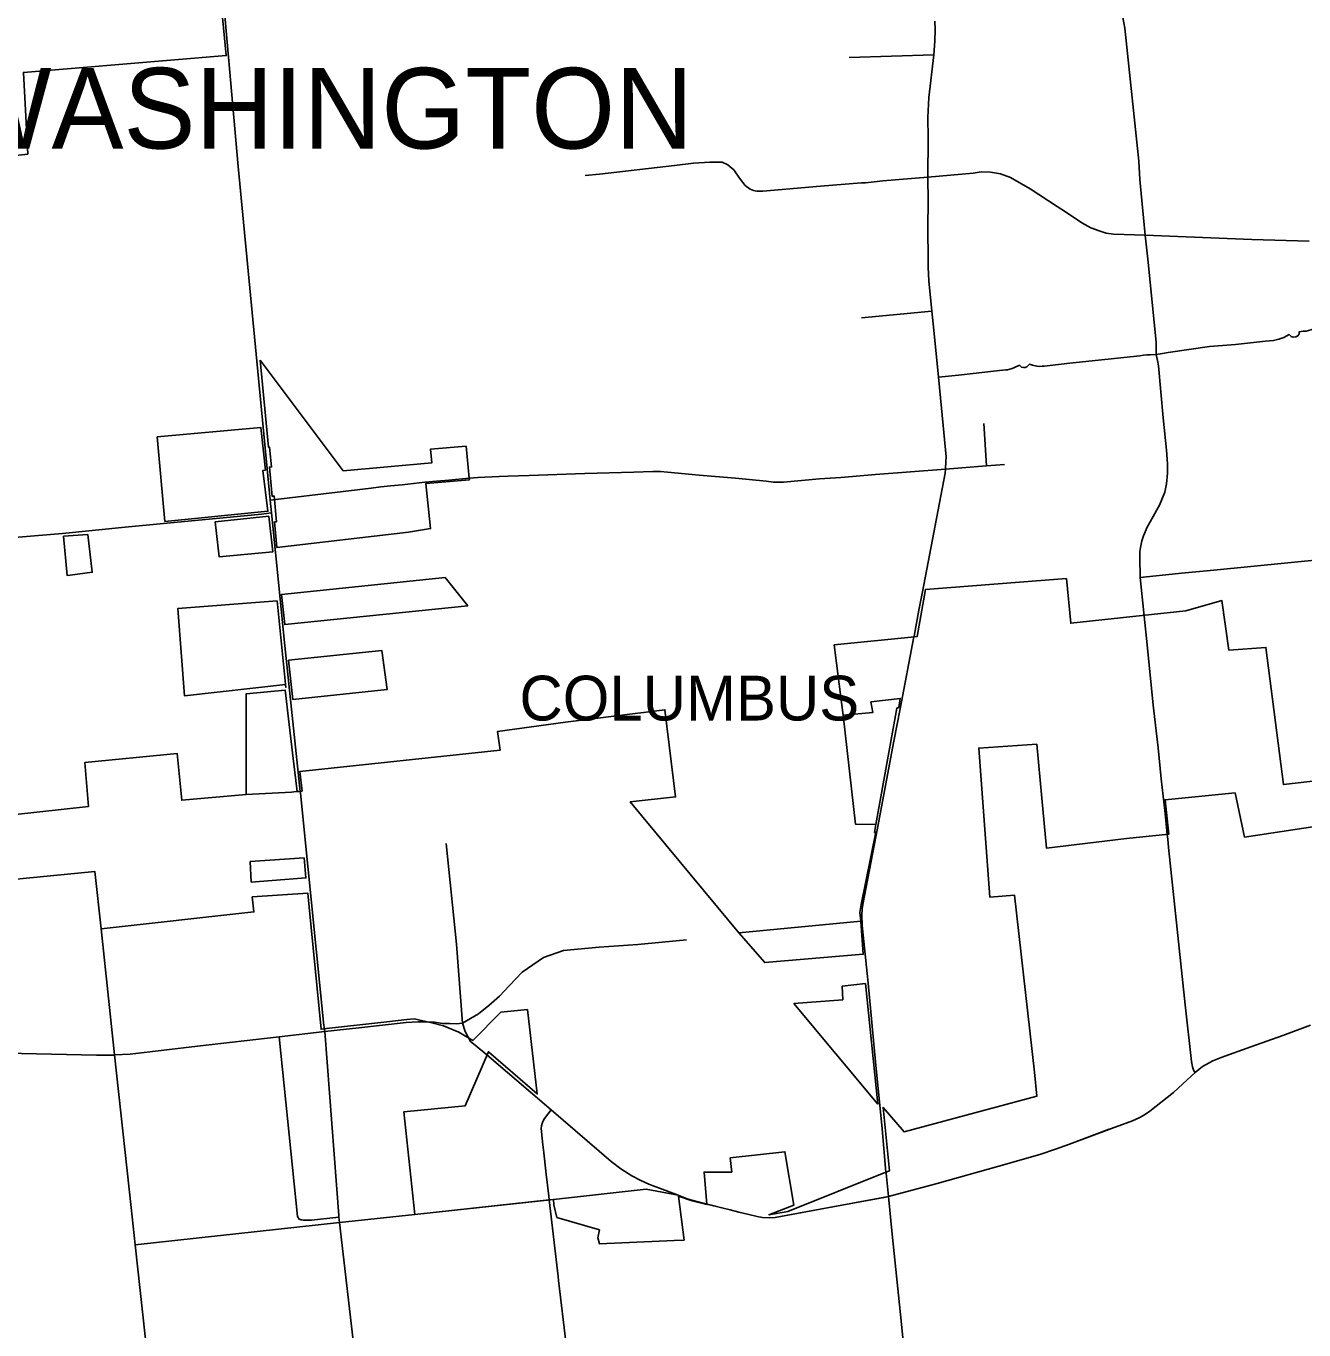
# Model space of a CAD drawing. Extents: x 1729596 to 1934326, y 644115 to 911751.
# Drawn here: x 1774170 to 1788422, y 747751 to 762296 of the extents above; entities that cross this region are included whole.
import ezdxf

# ---------------------------------------------------------------- set-up
doc = ezdxf.new("R2010")
doc.units = 0
for name, color, linetype in [('GM_X_City_Street', 7, 'Continuous'), ('GM_X_Corporation', 7, 'Continuous'), ('GM_X_Corporation_Text', 7, 'Continuous'), ('GM_X_County_Road', 7, 'Continuous'), ('GM_X_Township', 7, 'Continuous'), ('GM_X_Township_Road', 7, 'Continuous'), ('GM_X_Township_Text', 7, 'Continuous')]:
    doc.layers.add(name, color=color, linetype=linetype)

msp = doc.modelspace()

# ---------------------------------------------------------------- linework, layer by layer
at = {"layer": 'GM_X_City_Street'}
for points in [[(1776894, 757007), (1776536, 760730), (1776379, 762498), (1776312, 763238), (1776297, 763289)], [(1784074, 755492), (1784128, 755781), (1784167, 755984), (1784420, 757310), (1784425, 757355), (1784429, 757440), (1784431, 757489), (1784381, 758034), (1784347, 758381), (1784296, 758904), (1784274, 759116), (1784240, 759453), (1784230, 759608), (1784232, 759677), (1784229, 760052), (1784230, 760338), (1784227, 760609), (1784231, 761045), (1784227, 761277), (1784240, 761501), (1784293, 761975), (1784305, 762129), (1784308, 762257), (1784306, 762353)], [(1786597, 756146), (1786591, 756364), (1786591, 756433), (1786599, 756480), (1786616, 756555), (1786633, 756609), (1786673, 756706), (1786740, 756826), (1786781, 756898), (1786810, 756950), (1786870, 757096), (1786891, 757189), (1786900, 757307), (1786900, 757411), (1786891, 757566), (1786854, 757927), (1786800, 758507), (1786789, 758566), (1786774, 758633), (1786775, 758765), (1786733, 759178), (1786683, 759695), (1786650, 759962), (1786616, 760352), (1786592, 760584), (1786580, 760788), (1786424, 762272), (1786390, 762450)], [(1783351, 761947), (1784293, 761975)], [(1781403, 760741), (1781614, 760766), (1781798, 760777), (1781933, 760777), (1781997, 760747), (1782023, 760726)], [(1780404, 760630), (1780564, 760644), (1781403, 760741)], [(1782023, 760726), (1782065, 760691), (1782129, 760598), (1782192, 760517), (1782245, 760477), (1782283, 760463), (1782319, 760456), (1782381, 760453)], [(1783489, 760546), (1783531, 760549), (1783727, 760569), (1784227, 760609)], [(1784227, 760609), (1784735, 760656), (1784822, 760669), (1784927, 760665), (1785037, 760648), (1785151, 760606), (1785370, 760479), (1785672, 760283), (1785762, 760223), (1785944, 760103), (1786045, 760047), (1786138, 760011), (1786218, 759985), (1786298, 759975), (1786650, 759962), (1787842, 759914), (1788482, 759895)], [(1782381, 760453), (1782386, 760453), (1783031, 760512), (1783489, 760546)], [(1783488, 759043), (1784274, 759116)], [(1788366, 758855), (1788370, 758860), (1788370, 758887), (1788413, 758891), (1788448, 758894), (1788498, 758907), (1788586, 758939), (1788903, 759054), (1789110, 759123)], [(1785443, 758502), (1785447, 758501), (1785472, 758500), (1785504, 758503), (1785525, 758504), (1785812, 758536), (1786594, 758619), (1786632, 758624), (1786670, 758627), (1786708, 758629), (1786774, 758633), (1786846, 758644), (1786908, 758654), (1787368, 758722), (1787661, 758743), (1787994, 758780), (1788083, 758790), (1788142, 758802), (1788198, 758823), (1788258, 758854), (1788279, 758834), (1788304, 758825), (1788331, 758828), (1788354, 758841), (1788366, 758855)], [(1784347, 758381), (1784569, 758402), (1784992, 758452), (1785099, 758461)], [(1785099, 758461), (1785117, 758463), (1785168, 758475), (1785196, 758486), (1785249, 758513), (1785274, 758493), (1785296, 758489), (1785314, 758489), (1785332, 758496), (1785348, 758508), (1785360, 758524), (1785395, 758514), (1785443, 758502)], [(1784883, 757389), (1784852, 757862)], [(1784425, 757355), (1784883, 757389), (1785083, 757404)], [(1779113, 757254), (1779207, 757260), (1779446, 757273), (1779545, 757275), (1779780, 757281), (1780402, 757304), (1780947, 757321), (1781160, 757328), (1781202, 757328), (1781247, 757327), (1781325, 757320), (1781601, 757295), (1781679, 757288), (1782081, 757251), (1782426, 757218), (1782507, 757210), (1782570, 757208), (1782617, 757210), (1783021, 757244), (1783259, 757262), (1783644, 757292), (1784425, 757355)], [(1776906, 756865), (1776894, 757007)], [(1773219, 756522), (1773341, 756531), (1773503, 756545), (1774575, 756635), (1775276, 756706), (1776795, 756852), (1776906, 756865)], [(1777229, 753738), (1777227, 753759), (1777049, 755454), (1776999, 755942), (1776906, 756865)], [(1787022, 756188), (1787058, 756192), (1787419, 756227), (1788657, 756348), (1789032, 756388), (1789041, 756389)], [(1786597, 756146), (1787022, 756188)], [(1786678, 755355), (1786597, 756146)], [(1783762, 749500), (1783761, 749510), (1783717, 749993), (1783644, 750742), (1783561, 751619), (1783496, 752262), (1783491, 752376), (1783496, 752450), (1783504, 752498), (1783666, 753347), (1783850, 754318), (1783919, 754680), (1784072, 755481), (1784074, 755492)], [(1786913, 753133), (1786903, 753225), (1786897, 753277), (1786885, 753396), (1786873, 753510), (1786829, 753900), (1786798, 754245), (1786742, 754722), (1786678, 755355)], [(1777494, 751131), (1777492, 751145), (1777229, 753738)], [(1779038, 751174), (1778972, 752054), (1778854, 753177)], [(1787208, 750621), (1787194, 750642), (1787178, 750687), (1787167, 750746), (1787099, 751377), (1786983, 752466), (1786913, 753133)], [(1779038, 751174), (1779218, 751278), (1779333, 751371), (1779450, 751475), (1779560, 751591), (1779705, 751741), (1779942, 751906), (1780164, 751983), (1780561, 752019), (1780995, 752050), (1781537, 752102)], [(1777880, 751121), (1778410, 751180), (1778542, 751187), (1778625, 751187), (1778726, 751184), (1778813, 751170), (1778892, 751170), (1778972, 751167), (1779038, 751174), (1779069, 751080), (1779128, 750968), (1779180, 750929), (1779309, 750819), (1779309, 750819), (1780025, 750206)], [(1786252, 749989), (1786278, 749998), (1786509, 750083), (1786594, 750121), (1786638, 750146), (1786679, 750171), (1786705, 750190), (1786967, 750399), (1787071, 750497), (1787208, 750621), (1787293, 750689), (1787406, 750754), (1787499, 750790), (1787831, 750907), (1788188, 751036), (1788494, 751152)], [(1779935, 749817), (1779915, 749999), (1779919, 750028), (1779926, 750052), (1779935, 750077), (1779953, 750108), (1780025, 750206)], [(1780025, 750206), (1780696, 749630), (1780803, 749549), (1780925, 749469), (1781028, 749416), (1781115, 749377)], [(1780000, 749243), (1779970, 749490), (1779941, 749760), (1779935, 749817)], [(1781115, 749377), (1781135, 749369), (1781294, 749308), (1781443, 749254), (1781462, 749247)], [(1781462, 749247), (1781556, 749211), (1781667, 749178), (1781762, 749153), (1781816, 749141)], [(1782643, 749027), (1783268, 749142), (1783736, 749229)], [(1783922, 747924), (1783831, 748818)], [(1780386, 745952), (1780326, 746496), (1780278, 746873), (1780110, 748302)], [(1784024, 746925), (1783922, 747924)]]:
    msp.add_lwpolyline(points, dxfattribs=at)
at = {"layer": 'GM_X_Corporation'}
for points in [[(1772730, 760702), (1774189, 760869), (1774141, 761779), (1776402, 761968), (1776281, 763207), (1776046, 763174), (1775267, 763080), (1775267, 763099), (1774207, 762980), (1774134, 763952)], [(1773437, 753432), (1774866, 753591), (1774825, 754079), (1775856, 754180), (1775906, 753660), (1776624, 753722), (1777130, 753751), (1777182, 753756), (1777187, 753756), (1777192, 753756), (1777203, 753757), (1777227, 753759), (1777248, 753761), (1777222, 753980), (1779459, 754220), (1779429, 754427), (1780187, 754529), (1781295, 754669), (1781415, 753697), (1780909, 753642), (1782119, 752179), (1782408, 751849), (1783508, 751942), (1783479, 752309), (1783471, 752408), (1783484, 752497), (1783649, 753302), (1783633, 753301), (1783649, 753390), (1783882, 754688), (1783903, 754693), (1783921, 754795), (1783593, 754757), (1783615, 754639), (1783284, 754607), (1783265, 754751), (1783184, 755392), (1784040, 755478), (1784107, 755485), (1784200, 756011), (1785774, 756133), (1785821, 755634), (1786620, 755722), (1787106, 755772), (1787508, 755887), (1787585, 755334), (1787998, 755364), (1788193, 753835), (1789563, 753993)], [(1789563, 753993), (1788193, 753835), (1787998, 755364), (1787585, 755334), (1787508, 755887), (1787106, 755772), (1786620, 755722), (1785821, 755634), (1785774, 756133), (1784200, 756011), (1784107, 755485), (1784040, 755478), (1783184, 755392), (1783265, 754751), (1783284, 754607), (1783421, 753391), (1783649, 753390), (1783633, 753301), (1783649, 753302), (1783484, 752497), (1783471, 752408), (1783479, 752309), (1782119, 752179), (1780909, 753642), (1781415, 753697), (1781295, 754669), (1780187, 754529), (1779429, 754427), (1779459, 754220), (1777222, 753980), (1777248, 753761), (1777227, 753759), (1777203, 753757), (1777192, 753756), (1777150, 754125), (1777091, 754630), (1777072, 754794), (1777061, 754886), (1776626, 754848), (1776624, 753722), (1775906, 753660), (1775856, 754180), (1774825, 754079), (1774866, 753591), (1773437, 753432)], [(1789671, 753539), (1787760, 753249), (1787654, 753742), (1786874, 753665), (1786906, 753382), (1786916, 753283), (1786443, 753233), (1785553, 753125), (1785499, 753683), (1785442, 754285), (1784796, 754242), (1784920, 752578), (1785195, 752599), (1785416, 750625), (1785444, 750360), (1783963, 749959), (1783729, 750233), (1783799, 749524), (1783741, 749503), (1782666, 749072), (1782456, 749036), (1782732, 749144), (1782633, 749738), (1782024, 749670), (1782040, 749512), (1781732, 749512), (1781763, 749148), (1781598, 749189), (1781445, 749241), (1781509, 748753), (1781398, 748749), (1780567, 748710), (1780546, 748779), (1780565, 748866), (1780090, 749006), (1780055, 749146), (1780051, 749207), (1778506, 749039), (1778382, 750183), (1779068, 750252), (1779327, 750854), (1779872, 750383), (1779761, 751324), (1779466, 751295), (1779153, 750981), (1778998, 751072), (1778827, 751143), (1778680, 751179), (1778562, 751205), (1778501, 751220), (1778415, 751215), (1778192, 751189), (1777521, 751114), (1777461, 751105), (1777328, 752466), (1777311, 752624), (1776693, 752582), (1776711, 752414), (1775007, 752225), (1774938, 752864), (1772077, 752586)]]:
    msp.add_lwpolyline(points, dxfattribs=at)
for points in [[(1776781, 758571), (1776874, 757598), (1776884, 757599), (1776909, 757379), (1776884, 757376), (1776915, 757049), (1776937, 757054), (1776962, 756765), (1776941, 756764), (1776966, 756480), (1778434, 756650), (1778682, 756690), (1778628, 757192), (1779114, 757236), (1779113, 757254), (1779078, 757609), (1778681, 757577), (1778697, 757425), (1777708, 757333)], [(1775632, 757715), (1775719, 756770), (1776867, 756883), (1776810, 757337), (1776839, 757343), (1776787, 757819)], [(1776879, 756830), (1776278, 756765), (1776322, 756377), (1776922, 756430)], [(1774587, 756604), (1774629, 756166), (1774663, 756170), (1774909, 756203), (1774860, 756623)], [(1779096, 755830), (1778843, 756143), (1777018, 755954), (1777056, 755620)], [(1776970, 755885), (1775862, 755797), (1775938, 754823), (1777065, 754950), (1777068, 754919)], [(1777098, 755224), (1777144, 754785), (1778199, 754896), (1778137, 755331)], [(1776671, 752975), (1776681, 752746), (1777291, 752794), (1777271, 753017)], [(1783531, 751616), (1783273, 751584), (1783278, 751434), (1782734, 751391), (1783671, 750271)]]:
    msp.add_lwpolyline(points, close=True, dxfattribs=at)
at = {"layer": 'GM_X_County_Road'}
for points in [[(1776894, 757007), (1777705, 757105), (1778018, 757141), (1778128, 757155), (1778233, 757166), (1778365, 757180), (1778492, 757194), (1778619, 757207), (1778747, 757219), (1778884, 757232), (1779113, 757254)], [(1775150, 750817), (1775158, 750818), (1775331, 750827), (1776081, 750915), (1776992, 751020), (1777501, 751079)], [(1777657, 749027), (1777501, 751079), (1777496, 751112), (1777494, 751131)], [(1777501, 751079), (1777880, 751121)], [(1773615, 750844), (1774956, 750814), (1775150, 750817)], [(1783788, 749238), (1784330, 749384), (1785018, 749578), (1785478, 749709), (1785651, 749768), (1785808, 749822), (1786252, 749989)], [(1783831, 748818), (1783788, 749238), (1783762, 749500)], [(1780110, 748302), (1780105, 748345), (1780004, 749202), (1780000, 749243)], [(1781816, 749141), (1781932, 749114), (1782022, 749091), (1782121, 749066), (1782233, 749039), (1782323, 749016), (1782384, 749005), (1782462, 749000), (1782524, 749005), (1782643, 749027)], [(1783736, 749229), (1783788, 749238)], [(1777838, 747032), (1777838, 747047), (1777844, 747345), (1777839, 747438), (1777665, 748948), (1777658, 749009), (1777657, 749027)]]:
    msp.add_lwpolyline(points, dxfattribs=at)
at = {"layer": 'GM_X_Township'}
for points in [[(1769596, 752863), (1772003, 753500), (1772077, 752586), (1774938, 752864), (1775007, 752225), (1775158, 750818), (1775343, 749117), (1775388, 748700)], [(1776185, 741398), (1775388, 748700), (1777665, 748948), (1778506, 749039), (1780004, 749202), (1780051, 749207), (1781085, 749320), (1781443, 749254), (1781556, 749211), (1781667, 749178), (1781762, 749153), (1781932, 749114), (1782022, 749091), (1782121, 749066), (1782233, 749039), (1782323, 749016), (1782384, 749005), (1782462, 749000), (1782524, 749005), (1783268, 749142), (1783788, 749238), (1784330, 749384), (1785018, 749578), (1785478, 749709), (1785651, 749768), (1785808, 749822), (1786278, 749998), (1786509, 750083), (1786594, 750121), (1786638, 750146), (1786679, 750171), (1786705, 750190), (1786967, 750399), (1787071, 750497), (1787208, 750621), (1787293, 750689), (1787406, 750754), (1787499, 750790), (1787831, 750907), (1788188, 751036), (1788494, 751152)]]:
    msp.add_lwpolyline(points, dxfattribs=at)
at = {"layer": 'GM_X_Township_Road'}
for points in [[(1777244, 748978), (1777239, 748978), (1777216, 748985), (1777199, 749015), (1776992, 751020)], [(1777658, 749009), (1777355, 748974), (1777264, 748974), (1777244, 748978)]]:
    msp.add_lwpolyline(points, dxfattribs=at)

# ---------------------------------------------------------------- texts
at = {"layer": 'GM_X_Corporation_Text'}
msp.add_text('COLUMBUS', height=500, rotation=0, dxfattribs=at).set_placement((1779673, 754549))
at = {"layer": 'GM_X_Township_Text'}
msp.add_text('WASHINGTON', height=900, rotation=0, dxfattribs=at).set_placement((1773318, 760930))

doc.saveas('drawing.dxf')
